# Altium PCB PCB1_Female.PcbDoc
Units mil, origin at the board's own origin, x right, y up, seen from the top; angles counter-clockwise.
Board outline 945.03 x 2608.03 mil, 2 copper layers (Top Layer, Bottom Layer); 4 components, 50 nets, 100 pads, 0 vias.
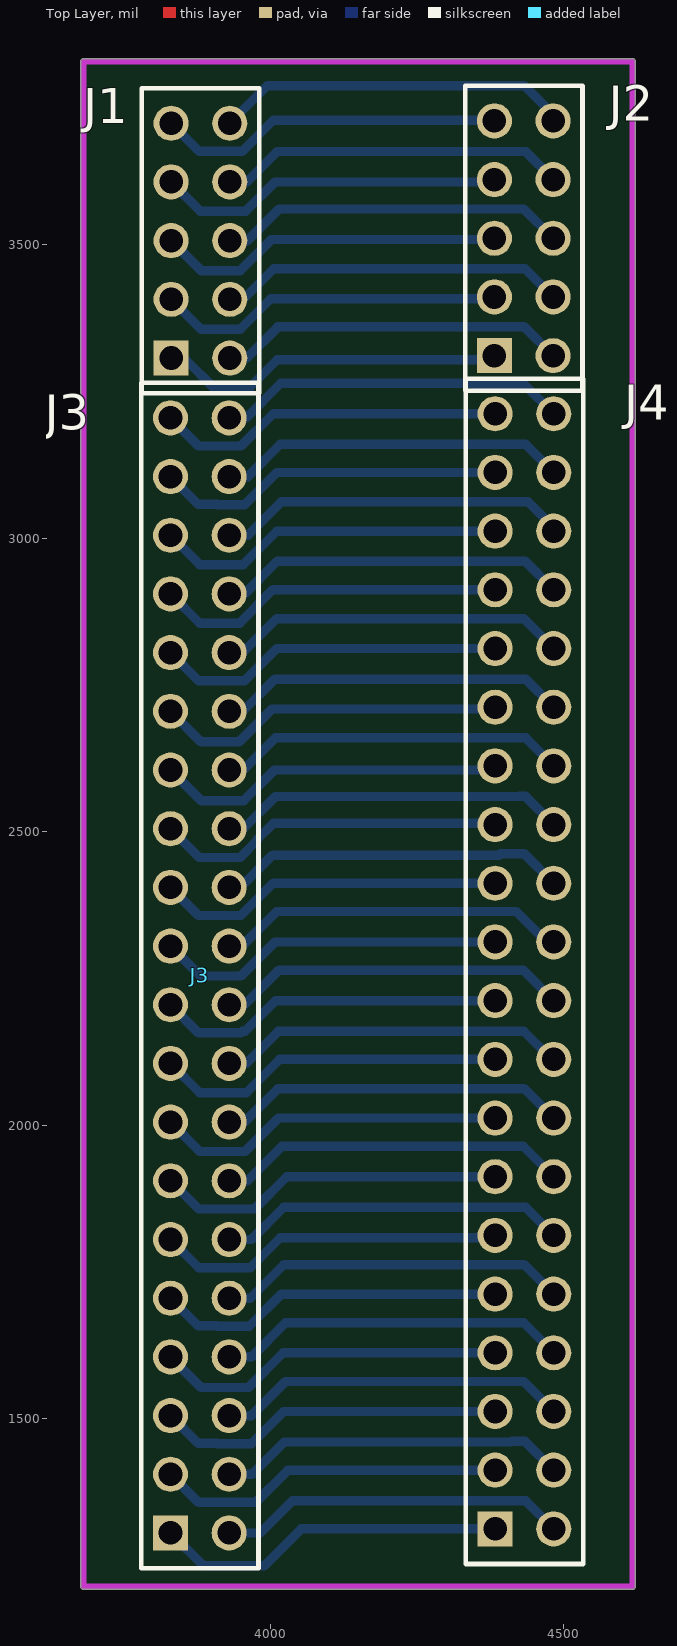
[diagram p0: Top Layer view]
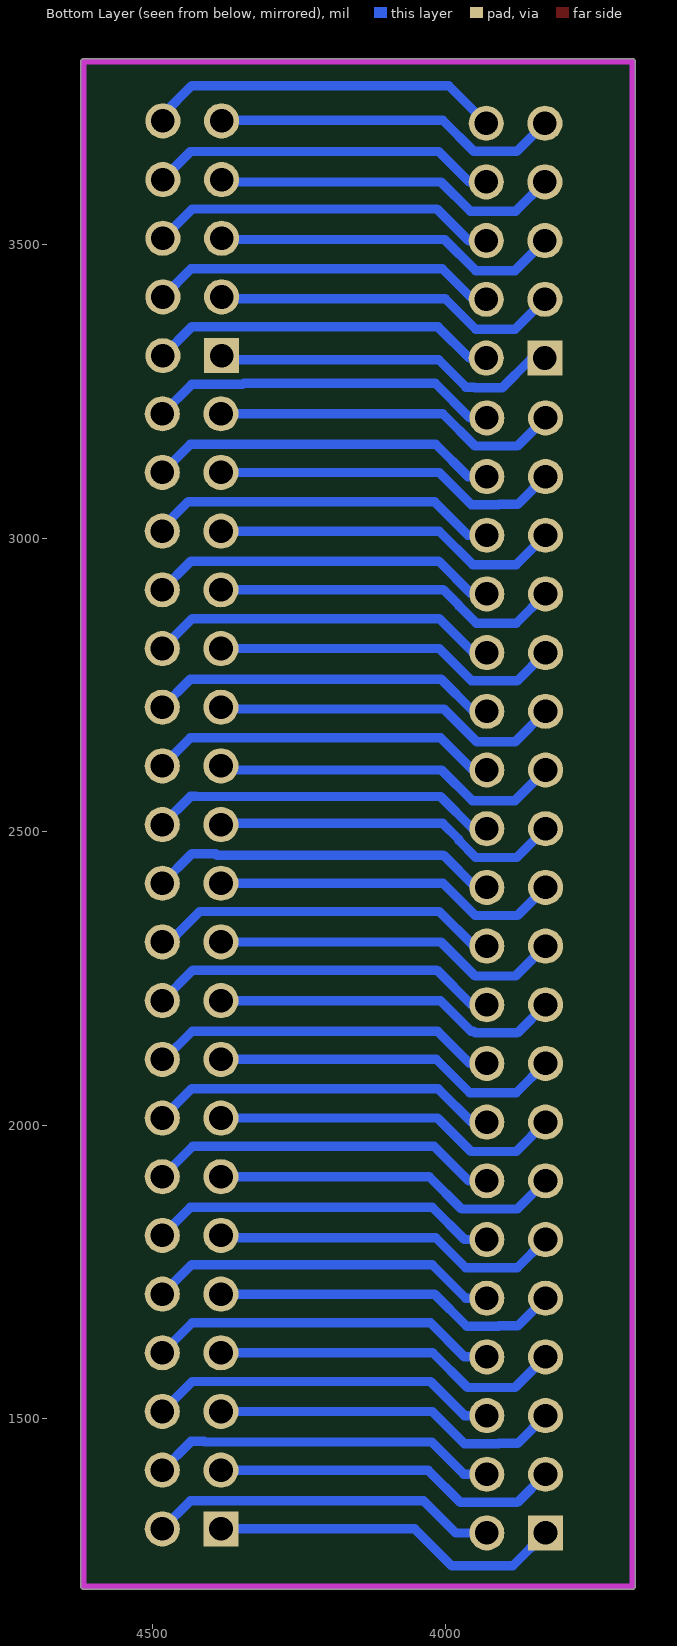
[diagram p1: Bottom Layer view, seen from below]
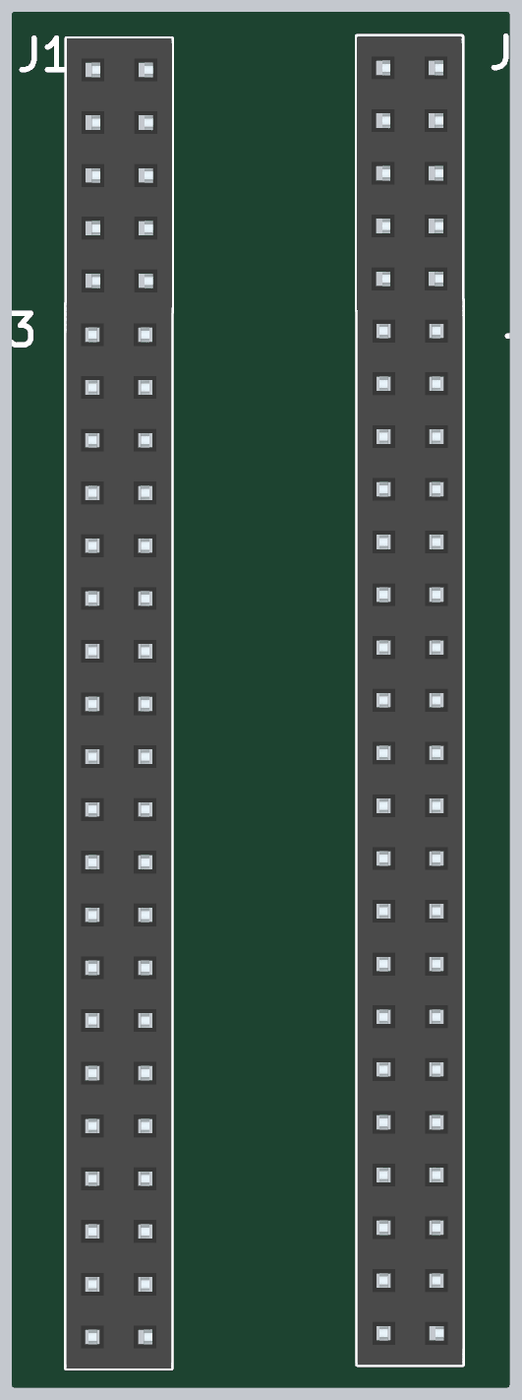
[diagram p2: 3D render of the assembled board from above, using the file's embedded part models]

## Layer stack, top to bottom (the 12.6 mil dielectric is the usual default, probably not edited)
Top Solder: solder mask 0.4, Solder Resist, Dk 3.5
Top Layer: signal copper 1.4
Dielectric 1: dielectric 12.6, FR-4, Dk 4.8
Bottom Layer: signal copper 1.4
Bottom Solder: solder mask 0.4, Solder Resist, Dk 3.5

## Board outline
3676.99,1214 3676.98,3812 cw(c3682,3812) 3682,3817.01 4617,3817.01 cw(c4617,3812) 4622.01,3812 4622.01,3804 4622.02,1214 cw(c4617,1214) 4617,1208.98 3682,1208.98 cw(c3682,1214)

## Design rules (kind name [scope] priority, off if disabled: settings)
Clearance [All] p1: gap=10 ignorepadtopadclearanceinfootprint=FALSE except(0: Arc-Hole Track-Hole SMDPad-Hole THPad-Hole Via-Hole Fill-Hole Poly-Hole Region-Hole Text-Hole)
PolygonConnect [All] p1: connectstyle=Relief reliefconductorwidth=10 reliefentries=4 polygonreliefangle="90 Angle" airgapwidth=10
RoomDefinition Sheet1_Female_stm32 [InComponentClass('Sheet1_Female_stm32')] p1: confinementstyle=ConfineIn formatcopy=TRUE lockcomponents=FALSE outline 7045,1060 8040,1060 8040,3200 7045,3200
RoutingVias [All] p1: holewidth=28 width=50 viastyle="Through Hole" minholewidth=28 minwidth=50 maxholewidth=28 maxwidth=50
SolderMaskExpansion [All] p1: expansion=4
Width [All] p1: maxlimit=16 minlimit=10 preferedwidth=16 toplayer_maxwidth=10 toplayer_prefwidth=10 bottomlayer_minwidth=16 minimp=50.000000 maximp=50.000000 favimp=50.000000
30 further rules are at their usual default settings.

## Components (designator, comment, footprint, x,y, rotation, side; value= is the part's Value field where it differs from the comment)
J1 "61301021821" 61301021821 3881,3507 r90 top
J2 "61301021821" 61301021821 4432,3511 r90 top
J3 "61304021821" 61304021821 3880,2255 r90 top
J4 "61304021821" 61304021821 4433,2262 r90 top

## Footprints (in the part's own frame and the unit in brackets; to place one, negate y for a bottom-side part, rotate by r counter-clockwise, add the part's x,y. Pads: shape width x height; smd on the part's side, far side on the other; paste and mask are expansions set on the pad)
61301021821 [mm] "10 pins, dual row, straight, gold plating"
  rect 1.52x1.52 hole 1.02: 1(-5.08,1.27)
  round 1.52 hole 1.02: 2(-2.54,1.27) 3(0,1.27) 4(2.54,1.27) 5(5.08,1.27) 6(-5.08,-1.27) 7(-2.54,-1.27) 8(0,-1.27) 9(2.54,-1.27) 10(5.08,-1.27)
  silkscreen extent -6.6,-2.54 6.6,2.54, body extent -6.6,-2.54 6.6,2.54, height 8.45
61304021821 [mm] "40 pins, dual row, straight, gold plating"
  rect 1.52x1.52 hole 1.02: 1(-24.13,1.27)
  round 1.52 hole 1.02: 2(-21.59,1.27) 3(-19.05,1.27) 4(-16.51,1.27) 5(-13.97,1.27) 6(-11.43,1.27) 7(-8.89,1.27) 8(-6.35,1.27) 9(-3.81,1.27) 10(-1.27,1.27) 11(1.27,1.27) 12(3.81,1.27) 13(6.35,1.27) 14(8.89,1.27) 15(11.43,1.27) 16(13.97,1.27) 17(16.51,1.27) 18(19.05,1.27) 19(21.59,1.27) 20(24.13,1.27) 21(-24.13,-1.27) 22(-21.59,-1.27) 23(-19.05,-1.27) 24(-16.51,-1.27) 25(-13.97,-1.27) 26(-11.43,-1.27) 27(-8.89,-1.27) 28(-6.35,-1.27) 29(-3.81,-1.27) 30(-1.27,-1.27) 31(1.27,-1.27) 32(3.81,-1.27) 33(6.35,-1.27) 34(8.89,-1.27) 35(11.43,-1.27) 36(13.97,-1.27) 37(16.51,-1.27) 38(19.05,-1.27) 39(21.59,-1.27) 40(24.13,-1.27)
  silkscreen extent -25.65,-2.54 25.65,2.54, body extent -25.65,-2.54 25.65,2.54, height 8.45

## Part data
J1 J2: library part "JP5x2 2.54MM", "2.54 mm Dual Socket Header, 10p"
J3 J4: library part "JP20x2 2.54MM", "2.54 mm Dual Socket Header, 40p"

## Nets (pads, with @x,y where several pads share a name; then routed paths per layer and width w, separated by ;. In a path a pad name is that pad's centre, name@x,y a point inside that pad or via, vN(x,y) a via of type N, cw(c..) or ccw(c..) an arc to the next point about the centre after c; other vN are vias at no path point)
3V1: J1.8 J2.8 | length 594.1
  Bottom Layer w16: J1.8 3961,3507 4015,3561 4432,3561 J2.8
3V2: J1.3 J2.3 | length 594.9
  Bottom Layer w16: J1.3 3882,3456 3949,3456 4002,3509 4380,3509 J2.3
5V1: J1.7 J2.7 | length 592.4
  Bottom Layer w16: J1.7 3954,3407 4006,3459 4434,3459 J2.7
5V2: J1.2 J2.2 | length 594.9
  Bottom Layer w16: J1.2 3882,3356 3949,3356 4001,3408 4379,3408 J2.2
BOOT0: J3.26 J4.26 | length 595.6
  Bottom Layer w16: J3.26 3968,1805 4022.92,1859.92 4435.08,1859.92 J4.26
GND1: J3.40 J4.40 | length 599
  Bottom Layer w16: J3.40 3959,3205 4018,3264 4343.7,3264 4345.62,3262.08 4432.92,3262.08 J4.40
GND2: J3.20 J4.20 | length 595.6
  Bottom Layer w16: J3.20 3877.92,3157.08 3950.08,3157.08 4005,3212 J4.20
GND3: J1.6 J2.6 | length 593.2
  Bottom Layer w16: J1.6 3960,3307 4013,3360 4433,3360 J2.6
GND4: J1.1 J2.1 | length 594.8
  Bottom Layer w16: J1.1@3831,3304 3856,3304 3903.92,3256.08 3950.85,3256.08 3951.77,3257 3966,3257 3966,3258 4012,3304 4377,3304 J2.1@4383,3310
PA8: J3.37 J4.37 | length 596.5
  Bottom Layer w16: J3.37 3956,2905 4012,2961 4434,2961 J4.37
PA9: J3.17 J4.17 | length 597.8
  Bottom Layer w16: J3.17 3880,2855 3947.77,2855 3977.92,2885.15 3977.92,2885.92 4004,2912 J4.17
PA10: J3.36 J4.36 | length 598.1
  Bottom Layer w16: J3.36 3953,2805 4011,2863 4432,2863 J4.36
PA13: J3.16 J4.16 | length 595.6
  Bottom Layer w16: J3.16 3877.92,2757.08 3956.08,2757.08 4011,2812 J4.16
PA14: J3.35 J4.35 | length 595.6
  Bottom Layer w16: J3.35 3953,2705 4007.92,2759.92 4421.84,2759.92 4435.08,2759.92 J4.35
PA15: J3.15 J4.15 | length 599
  Bottom Layer w16: J3.15 3882.08,2652.92 3946.92,2652.92 4003,2709 4380,2709 J4.15
PB3: J3.9 J4.9 | length 597.3
  Bottom Layer w16: J3.9 3880,2055 3959,2055 4016,2112 J4.9
PB4: J3.28 J4.28 | length 597.3
  Bottom Layer w16: J3.28 3956,2005 4013,2062 4433,2062 J4.28
PB5: J3.8 J4.8 | length 597.3
  Bottom Layer w16: J3.8 3880,1955 3957,1955 4014,2012 J4.8
PB6: J3.27 J4.27 | length 599
  Bottom Layer w16: J3.27 3961,1905 4020.08,1964.08 4430.92,1964.08 J4.27
PB7: J3.7 J4.7 | length 595.7
  Bottom Layer w16: J3.7 3878,1857 3973,1857 4028,1912 J4.7
PB8: J3.25 J4.25 | length 597.3
  Bottom Layer w16: J3.25 3966,1705 4023,1762 4433,1762 J4.25
PB9: J3.5 J4.5 | length 595.6
  Bottom Layer w16: J3.5 3877,1658 3909.23,1658 3910.15,1657.08 3964.08,1657.08 4019,1712 J4.5
PC6: J3.39 J4.39 | length 595.6
  Bottom Layer w16: J3.39 3962,3105 4016.92,3159.92 4435.08,3159.92 J4.39
PC7: J3.19 J4.19 | length 595.6
  Bottom Layer w16: J3.19 3877,3058 3909.23,3058 3910.15,3057.08 3956.08,3057.08 4011,3112 J4.19
PC8: J3.38 J4.38 | length 600.8
  Bottom Layer w16: J3.38 3962,3005 4019,3062 4439,3062 4483,3018 J4.38
PC9: J3.18 J4.18 | length 597.3
  Bottom Layer w16: J3.18 3880,2955 3954,2955 4011,3012 J4.18
PC10: J3.34 J4.34 | length 595.6
  Bottom Layer w16: J3.34 3954,2605 4008.92,2659.92 4435.08,2659.92 J4.34
PC11: J3.14 J4.14 | length 599
  Bottom Layer w16: J3.14 3882.08,2552.92 3954.92,2552.92 4007,2605 4376,2605 J4.14
PC12: J3.33 J4.33 | length 595.7
  Bottom Layer w16: J3.33 3954,2505 4008.92,2559.92 4424.92,2559.92 4425,2560 4435,2560 J4.33
PC13: J3.1 J4.1 | length 602.3
  Bottom Layer w16: J3.1 3886,1249 3990,1249 4053,1312 J4.1
PC14: J1.10 J2.10 | length 608.8
  Bottom Layer w16: J1.10 3995,3771 4433,3771 4482,3722 J2.10
PC15: J1.5 J2.5 | length 593.2
  Bottom Layer w16: J1.5 3878.92,3659.08 3952.08,3659.08 4005,3712 4381,3712 J2.5
PD0: J3.13 J4.13 | length 599.2
  Bottom Layer w16: J3.13 3879,2456 3948.77,2456 3977.92,2485.15 3977.92,2486.92 4005,2514 4381,2514 J4.13
PD1: J3.32 J4.32 | length 597.3
  Bottom Layer w16: J3.32 3949,2405 4004,2460 4390,2460 4392,2462 4433,2462 J4.32
PD2: J3.12 J4.12 | length 595.6
  Bottom Layer w16: J3.12 3877.92,2357.08 3949.85,2357.08 4004.77,2412 J4.12
PD3: J3.31 J4.31 | length 599
  Bottom Layer w16: J3.31 3952,2305 4011,2364 4419,2364 4471,2312 J4.31
PD4: J3.11 J4.11 | length 598.1
  Bottom Layer w16: J3.11 3881,2254 3950,2254 4008,2312 J4.11
PD5: J3.30 J4.30 | length 599
  Bottom Layer w16: J3.30 3956,2205 4015,2264 4431,2264 J4.30
PD6: J3.10 J4.10 | length 595.6
  Bottom Layer w16: J3.10 3877.92,2157.08 3949.85,2157.08 3952.77,2160 3957,2160 4009,2212 J4.10
PD7: J3.29 J4.29 | length 595.6
  Bottom Layer w16: J3.29 3959,2105 4013.92,2159.92 4432.08,2159.92 4480,2112 J4.29
PE0: J3.24 J4.24 | length 598.1
  Bottom Layer w16: J3.24 3968,1605 4026,1663 4432,1663 J4.24
PE1: J3.4 J4.4 | length 599
  Bottom Layer w16: J3.4 3882.08,1552.92 3962.92,1552.92 4022,1612 J4.4
PE2: J3.23 J4.23 | length 598.1
  Bottom Layer w16: J3.23 3968,1505 4026,1563 4432,1563 J4.23
PE3: J3.3 J4.3 | length 595.6
  Bottom Layer w16: J3.3 3877,1458 3909.23,1458 3910.15,1457.08 3968.08,1457.08 4023,1512 J4.3
PE4: J3.22 J4.22 | length 596.5
  Bottom Layer w16: J3.22 3969,1405 4023.92,1459.92 4410.92,1459.92 4412,1461 4434,1461 J4.22
PE5: J3.2 J4.2 | length 595.6
  Bottom Layer w16: J3.2 3877.92,1357.08 3975.08,1357.08 4030,1412 J4.2
PE6: J3.21 J4.21 | length 595.6
  Bottom Layer w16: J3.21 3983,1305 4037.92,1359.92 4435.08,1359.92 J4.21
PH0: J1.9 J2.9 | length 592.9
  Bottom Layer w16: J1.9 3960,3607 4011.92,3658.92 4435.08,3658.92 4482,3612 J2.9
PH1: J1.4 J2.4 | length 594.1
  Bottom Layer w16: J1.4 3881,3557 3958,3557 4008,3607 4378,3607 J2.4
VDD: J3.6 J4.6 | length 595.7
  Bottom Layer w16: J3.6 3878,1757 3966,1757 4017,1808 4379,1808 J4.6

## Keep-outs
Keep-Out Layer:
  lines w10: 3682,1214 4617,1214 4617,3804 4617,3812 3682,3812 3682,1214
